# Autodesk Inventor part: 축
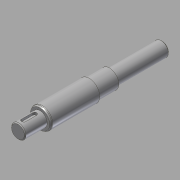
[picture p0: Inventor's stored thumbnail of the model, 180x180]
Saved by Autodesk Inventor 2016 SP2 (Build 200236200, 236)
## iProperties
Created: 2019-01
Part Number: 축
Material: 강철, 탄소
Document SubType Name: Modeling
Designer: mduedu
Density: 7.87 g/cm^3
Mass: 452.778 g
Surface Area: 120.904 cm^2
Volume: 57.5322 cm^3
Appearance: 강철
Author: mduedu
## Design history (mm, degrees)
sketch "스케치1"
  geometry: L1 (0, 0)-(26, 0); L2 (26, 0)-(26, 8.5); L3 (26, 8.5)-(0, 8.5); L4 (0, 8.5)-(0, 0); L5 (26, 0)-(84, 0); L6 (84, 0)-(84, 12.5); L7 (84, 12.5)-(26, 12.5); L8 (26, 12.5)-(26, 0); L9 (84, 0)-(108, 0); L10 (108, 0)-(108, 11); L11 (108, 11)-(84, 11); L12 (84, 11)-(84, 0); L13 (108, 0)-(170, 0); L14 (170, 0)-(170, 8.5); L15 (170, 8.5)-(108, 8.5); L16 (108, 8.5)-(108, 0)
  constraints: 32 end point, 8 parallel, 4 horizontal, 4 perpendicular
  dimensions: "d0" = 170 distance between parallel lines of L14 L4; "d2" = 26 distance of L2.end L3.end; "d3" = 24 distance of L10.end L11.end; "d4" = 62 distance of L14.end L15.end; "d5" = 17 diameter of L3 L1; "d6" = 25 diameter of L7 L5; "d7" = 22 diameter of L11 L9; "d8" = 17 diameter of L15 L13
revolve "회전1" sketch "스케치1" stored, may be unused: angle "d9" = 90 deg
node "작업 평면1"
sketch "스케치2" dims "d13" = 18
  geometry: L1 (6.5, -2.5)-(-6.5, -2.5); L2 (-6.5, -2.5)-(-6.5, 2.5); L3 (-6.5, 2.5)-(6.5, 2.5); L4 (6.5, 2.5)-(6.5, -2.5); L5 (13, 8.5)-(13, -8.5) reference; 3 further points
  constraints: 8 end point, 2 midpoint, 2 parallel, 2 vertical alignment, 1 horizontal, 1 horizontal alignment, 1 perpendicular, 4 other
  dimensions: "d10" = 5 distance between parallel lines of L3 L1; "d12" = 4 dimension on L5
extrude "돌출1" cut sketch "스케치2" distance "d14" = 3; taper "d15" = 0 deg
node "작업 평면2"
sketch "스케치3" dims "d19" = 18
  geometry: L1 (-24.5, -2.5)-(-11.5, -2.5); L2 (-11.5, -2.5)-(-11.5, 2.5); L3 (-11.5, 2.5)-(-24.5, 2.5); L4 (-24.5, 2.5)-(-24.5, -2.5); L5 (-31, 8.5)-(-31, -8.5) reference; 3 further points
  constraints: 8 end point, 2 midpoint, 2 parallel, 2 vertical alignment, 1 horizontal, 1 horizontal alignment, 1 perpendicular, 4 other
  dimensions: "d16" = 5 distance between parallel lines of L3 L1; "d18" = 4 dimension on L5
extrude "돌출2" cut sketch "스케치3" distance "d20" = 3; taper "d21" = 0 deg
chamfer "모따기1" distance "d22" = 1; stored, may be unused: second distance "d23" = 2, angle "d24" = 45 deg
chamfer "모따기2" distance "d25" = 2; stored, may be unused: second distance "d26" = 2, angle "d27" = 30 deg
fillet "모깎기2" dims "d30" = 2
node "솔리드1"
